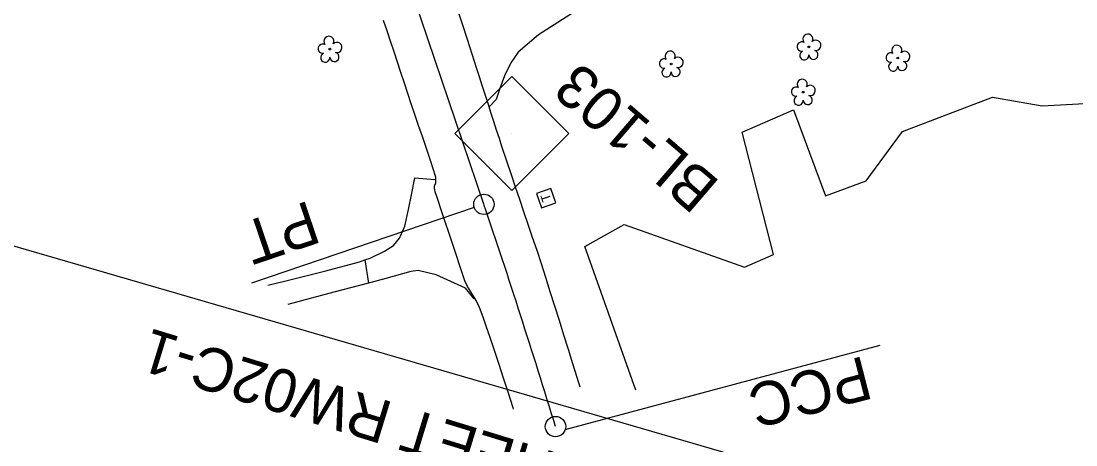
# Model space of a CAD drawing. Extents: x 478596 to 483012, y 490885 to 495165.
# Drawn here: x 481144.5 to 481532.8, y 491833.7 to 491989.7 of the extents above; entities that cross this region are included whole.
import ezdxf

# ---------------------------------------------------------------- set-up
doc = ezdxf.new("R2010")
doc.units = 0
for name, color, linetype in [('CTL Secondary Horizontal and Vertical CELL', 7, 'Continuous'), ('CTL Secondary Horizontal and Vertical Text', 7, 'Continuous'), ('Exist Horizontal Alignment', 7, 'Continuous'), ('Exist Roads EOP', 7, 'Continuous'), ('Exist Roads EOP Other', 7, 'Continuous'), ('Exist Roads Soil', 7, 'Continuous'), ('Exist Utilities Telephone Pedestal CELL', 7, 'Continuous'), ('Exist Vegetation Tree CELL', 7, 'Continuous'), ('Exist Vegetation Woods Line', 7, 'Continuous'), ('Matchline', 7, 'Continuous'), ('Matchline Text', 7, 'Continuous')]:
    doc.layers.add(name, color=color, linetype=linetype)

msp = doc.modelspace()

# ---------------------------------------------------------------- linework, layer by layer
at = {"layer": 'CTL Secondary Horizontal and Vertical CELL'}
msp.add_line((481325.02, 491948.27), (481325.02, 491948.27), dxfattribs=at)
msp.add_lwpolyline([(481304.16, 491948.34), (481325.13, 491969.3), (481346.13, 491948.3), (481325.16, 491927.33)], close=True, dxfattribs=at)
at = {"layer": 'Exist Horizontal Alignment'}
for p, q in [((481314.86, 491922.25), (481071.89, 492639.91)), ((481311.31, 491921.05), (481229.24, 491893.26)), ((481344.8, 491839.37), (481460.75, 491870.4))]:
    msp.add_line(p, q, dxfattribs=at)
for centre in [(481314.86, 491922.25), (481341.2, 491840.41)]:
    msp.add_circle(centre, 3.75, dxfattribs=at)
msp.add_arc((478607.84, 491005.76), 2857.95, 16.9803, 18.70399, dxfattribs=at)
at = {"layer": 'Exist Roads EOP'}
for points in [[(481305.3, 491993.45), (481307, 491988.34), (481308.72, 491983.02), (481310.42, 491977.68), (481312.13, 491972.24), (481313.07, 491969.29), (481314.07, 491966.16), (481315.15, 491962.84), (481316.25, 491959.47), (481317.33, 491956.15), (481318.38, 491952.9), (481319.41, 491949.72), (481320.41, 491946.63), (481321.37, 491943.68), (481323.17, 491938.2), (481324.83, 491933.21), (481326.38, 491928.63), (481327.9, 491924.18), (481329.46, 491919.58), (481331.05, 491914.89), (481332.66, 491910.18), (481334.28, 491905.38), (481335.89, 491900.45), (481337.52, 491895.38), (481339.16, 491890.17), (481340.83, 491884.88), (481342.52, 491879.56), (481344.21, 491874.24), (481345.87, 491868.93), (481347.51, 491863.68), (481349.12, 491858.56), (481350.22, 491855.06)], [(481325.76, 491846.84), (481325.6, 491847.35), (481323.8, 491853.03), (481322.1, 491858.29), (481320.45, 491863.33), (481318.76, 491868.39), (481317.14, 491873.17), (481315.7, 491877.36), (481314.55, 491880.67), (481313.24, 491884.23), (481312.04, 491886.81), (481310.67, 491889.06), (481308.84, 491891.95), (481307.83, 491894.13), (481306.18, 491898.83), (481304.35, 491904.53), (481303.26, 491907.88), (481302.06, 491911.52), (481300.75, 491915.45), (481299.53, 491919.08), (481297.61, 491924.77), (481296.94, 491926.8), (481296.73, 491927.62), (481296.68, 491928), (481296.66, 491928.37), (481296.67, 491928.71), (481296.71, 491929), (481296.78, 491929.26), (481296.98, 491929.66), (481297.06, 491929.86), (481297.12, 491930.08), (481297.16, 491930.3), (481297.2, 491930.84), (481297.19, 491931.53), (481297.11, 491932.25), (481297.04, 491932.57), (481295.32, 491938.07), (481293.47, 491943.55), (481292.18, 491947.27), (481290.79, 491951.3), (481289.43, 491955.28), (481288.11, 491959.2), (481286.83, 491963.07), (481285.57, 491966.91), (481284.31, 491970.75), (481283.04, 491974.6), (481281.77, 491978.44), (481280.5, 491982.28), (481279.22, 491986.13), (481277.93, 491989.98)]]:
    msp.add_lwpolyline(points, dxfattribs=at)
at = {"layer": 'Exist Roads EOP Other'}
msp.add_line((481271.02, 491901.75), (481272.39, 491893.22), dxfattribs=at)
for points in [[(481271.02, 491901.75), (481273.02, 491902.41), (481278.31, 491905.04), (481281.52, 491907.06), (481283.77, 491909.77), (481285.75, 491914.22), (481287.04, 491920.33), (481288.18, 491925.78), (481289.47, 491931.99), (481296.84, 491931.41)], [(481311.24, 491887.5), (481308.1, 491891.44), (481302.65, 491893.83), (481297.33, 491896.28), (481290.63, 491897.83), (481287.92, 491897.48), (481278.77, 491894.96), (481272.39, 491893.22)]]:
    msp.add_lwpolyline(points, dxfattribs=at)
at = {"layer": 'Exist Roads Soil'}
for points in [[(481350.89, 491994.81), (481334.92, 491984.69), (481327.44, 491978.21), (481324.81, 491974.3), (481322.48, 491969.54), (481320.76, 491964.95), (481319.34, 491960.85), (481316.92, 491958.3)], [(481235.32, 491892.43), (481241.95, 491894.14), (481256.6, 491897.81), (481269.02, 491901.08), (481271.02, 491901.75)], [(481272.39, 491893.22), (481259.56, 491889.85), (481242.71, 491885.38)]]:
    msp.add_lwpolyline(points, dxfattribs=at)
at = {"layer": 'Exist Utilities Telephone Pedestal CELL'}
msp.add_line((481337.73, 491924.43), (481337.73, 491924.43), dxfattribs=at)
msp.add_lwpolyline([(481341.3, 491922.79), (481339.45, 491928.07), (481334.17, 491926.22), (481336.02, 491920.94), (481341.3, 491922.79)], dxfattribs=at)
at = {"layer": 'Exist Vegetation Tree CELL'}
for p, q in [((481258.14, 491979.4), (481258.14, 491979.4)), ((481434.5, 491980.19), (481434.5, 491980.19)), ((481467.22, 491976.11), (481467.22, 491976.11)), ((481383.78, 491973.92), (481383.78, 491973.92)), ((481432.4, 491963.58), (481432.4, 491963.58))]:
    msp.add_line(p, q, dxfattribs=at)
for centre in [(481258.14, 491979.4), (481434.5, 491980.19), (481467.22, 491976.11), (481383.78, 491973.92), (481432.4, 491963.58)]:
    msp.add_circle(centre, 0.326, dxfattribs=at)
for centre, radius, start, end in [((481257.76, 491982.27), 1.86, 330.1651, 219.7134), ((481434.11, 491983.06), 1.86, 330.1651, 219.7134), ((481255.54, 491979.55), 1.73, 62.6636, 279.3457), ((481260.69, 491979.99), 1.9, 257.1011, 134.1999), ((481431.89, 491980.34), 1.73, 62.6636, 279.3457), ((481437.05, 491980.78), 1.9, 257.1011, 134.1999), ((481466.84, 491978.98), 1.86, 330.1651, 219.7134), ((481256.44, 491976.28), 1.69, 111.5671, 6.231), ((481259.82, 491976.5), 1.7, 181.2822, 74.56), ((481381.17, 491974.08), 1.73, 62.6636, 279.3457), ((481383.39, 491976.8), 1.86, 330.1651, 219.7134), ((481386.33, 491974.51), 1.9, 257.1011, 134.1999), ((481432.8, 491977.07), 1.69, 111.5671, 6.231), ((481436.17, 491977.29), 1.7, 181.2822, 74.56), ((481464.62, 491976.26), 1.73, 62.6636, 279.3457), ((481469.77, 491976.7), 1.9, 257.1011, 134.1999), ((481382.08, 491970.8), 1.69, 111.5671, 6.231), ((481385.45, 491971.02), 1.7, 181.2822, 74.56), ((481465.52, 491972.99), 1.69, 111.5671, 6.231), ((481468.89, 491973.21), 1.7, 181.2822, 74.56), ((481432.02, 491966.45), 1.86, 330.1651, 219.7134), ((481429.8, 491963.73), 1.73, 62.6636, 279.3457), ((481434.95, 491964.17), 1.9, 257.1011, 134.1999), ((481430.7, 491960.46), 1.69, 111.5671, 6.231), ((481434.07, 491960.68), 1.7, 181.2822, 74.56)]:
    msp.add_arc(centre, radius, start, end, dxfattribs=at)
at = {"layer": 'Exist Vegetation Woods Line'}
msp.add_lwpolyline([(481370.78, 491853.85), (481351.95, 491906.77), (481366.45, 491914.77), (481410.8, 491899.16), (481421.42, 491903.82), (481409.89, 491948.85), (481428.87, 491957.06), (481440.61, 491925.36), (481455.59, 491930.86), (481468.91, 491949.08), (481502.11, 491961.68), (481520.4, 491958.45), (481540.45, 491959.56), (481547.5, 491970.59), (481550.62, 491990.5), (481533.93, 492008.17), (481529.05, 492061.74), (481534.56, 492102.92), (481577.42, 492110.74)], dxfattribs=at)
at = {"layer": 'Matchline'}
msp.add_line((481045.53, 491934.93), (481525.69, 491795.49), dxfattribs=at)

# ---------------------------------------------------------------- texts
at = {"layer": 'CTL Secondary Horizontal and Vertical Text'}
msp.add_text('BL-103', height=16, rotation=139.3796, dxfattribs=at).set_placement((481402.29, 491930.23))
at = {"layer": 'Exist Horizontal Alignment'}
for s, rotation, p in [('PT', 198.704, (481250.53, 491923.77)), ('PCC', 194.4962, (481454.82, 491866.52))]:
    msp.add_text(s, height=16, rotation=rotation, dxfattribs=at).set_placement(p)
at = {"layer": 'Exist Utilities Telephone Pedestal CELL'}
msp.add_text('T', height=3.42, rotation=109.3364, dxfattribs=at).set_placement((481339.73, 491923.93))
at = {"layer": 'Matchline Text'}
msp.add_text('MATCHLINE SHEET RW02C-1', height=16, rotation=162.94, dxfattribs=at).set_placement((481479.79, 491788.44))

doc.saveas('drawing.dxf')
